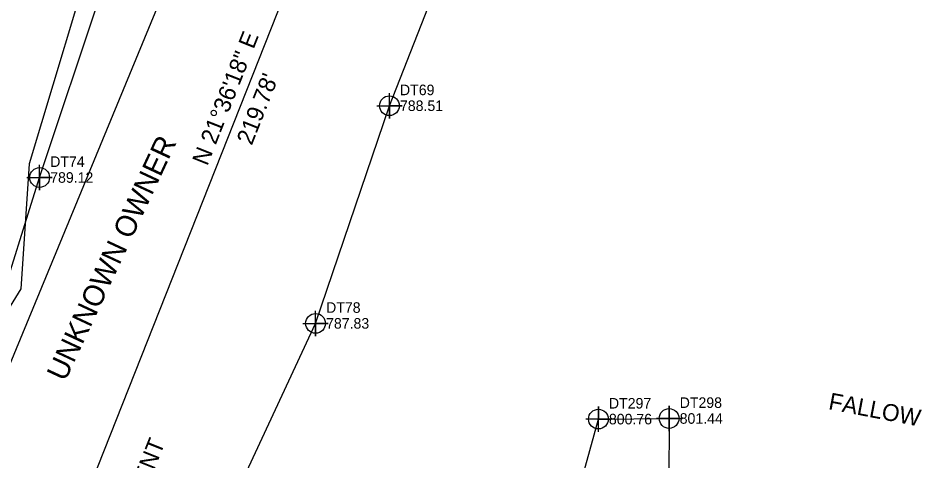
# Model space of a CAD drawing. Extents: x 1316460 to 1321645, y 684173 to 687077.
# Drawn here: x 1319633.3 to 1319847.6, y 686075.6 to 686180.5 of the extents above; entities that cross this region are included whole.
import ezdxf

# ---------------------------------------------------------------- set-up
doc = ezdxf.new("R2010")
doc.units = 0
for name, color, linetype in [('CTL Supplemental Horizontal and Vertical Cogo Elevation', 7, 'Continuous'), ('Exist Hydro Stream or Body of Water Cogo Elevation', 7, 'Continuous'), ('Exist Hydro Stream or Body of Water Cogo Number', 7, 'Continuous'), ('Exist Hydro Stream or Body of Water Cogo Point CELL', 7, 'Continuous'), ('Exist Hydrographic Stream Bed Cogo Number', 7, 'Continuous'), ('Exist Hydrographic Top of Bank Cogo Number', 7, 'Continuous'), ('Exist Hydrographic Top of Bank Cogo Point CELL', 7, 'Continuous'), ('Exist Hydrographic Water Edge Cogo Elevation', 7, 'Continuous'), ('Exist Hydrographic Water Surface Cogo Number', 7, 'Continuous'), ('Exist Property Line', 7, 'Continuous'), ('Exist Property Line Text', 7, 'Continuous'), ('Exist Property Owner Text', 7, 'Continuous'), ('Exist Vegetation Woods Line', 7, 'Continuous'), ('Exist Vegetation Woods Line Text', 7, 'Continuous')]:
    doc.layers.add(name, color=color, linetype=linetype)

msp = doc.modelspace()

# ---------------------------------------------------------------- linework, layer by layer
at = {"layer": 'CTL Supplemental Horizontal and Vertical Cogo Elevation'}
for points in [[(1319770.9, 686082.52), (1319770.9, 686088.52), (1319770.9, 686085.52), (1319773.9, 686085.52), (1319767.9, 686085.52)], [(1319787.68, 686082.67), (1319787.68, 686088.67), (1319787.68, 686085.67), (1319790.68, 686085.67), (1319784.68, 686085.67)]]:
    msp.add_lwpolyline(points, dxfattribs=at)
for centre in [(1319770.9, 686085.52), (1319787.68, 686085.67)]:
    msp.add_circle(centre, 2.34, dxfattribs=at)
at = {"layer": 'Exist Hydro Stream or Body of Water Cogo Point CELL'}
for points in [[(1319718.37, 686159.76), (1319724.37, 686159.76), (1319721.37, 686159.76), (1319721.37, 686156.76), (1319721.37, 686162.76)], [(1319635.45, 686142.76), (1319641.45, 686142.76), (1319638.45, 686142.76), (1319638.45, 686139.76), (1319638.45, 686145.76)], [(1319700.85, 686108.2), (1319706.85, 686108.2), (1319703.85, 686108.2), (1319703.85, 686105.2), (1319703.85, 686111.2)]]:
    msp.add_lwpolyline(points, dxfattribs=at)
for centre in [(1319721.37, 686159.76), (1319638.45, 686142.76), (1319703.85, 686108.2)]:
    msp.add_circle(centre, 2.34, dxfattribs=at)
at = {"layer": 'Exist Hydrographic Water Edge Cogo Elevation'}
for points in [[(1319609.37, 686060.81), (1319617.66, 686076.4), (1319638.45, 686142.76), (1319653.04, 686186.56), (1319674.85, 686240.81)], [(1319671.78, 686037.22), (1319683.32, 686064.04), (1319703.85, 686108.2), (1319721.37, 686159.76), (1319742.31, 686213.15)]]:
    msp.add_lwpolyline(points, dxfattribs=at)
at = {"layer": 'Exist Hydrographic Water Surface Cogo Number'}
for p, q in [((1319763.6, 686058.84), (1319770.9, 686085.52)), ((1319770.9, 686085.52), (1319787.68, 686085.67)), ((1319787.68, 686085.67), (1319787.52, 686046.5))]:
    msp.add_line(p, q, dxfattribs=at)
at = {"layer": 'Exist Property Line'}
for p, q in [((1319623.43, 686079.33), (1319824.68, 686565.61)), ((1319650.35, 686069.59), (1319731.27, 686273.93))]:
    msp.add_line(p, q, dxfattribs=at)
at = {"layer": 'Exist Vegetation Woods Line'}
msp.add_lwpolyline([(1319710.84, 686358.17), (1319684.48, 686276.05), (1319665.93, 686223.9), (1319652.82, 686201.99), (1319635.98, 686145.96), (1319634.02, 686116.41), (1319613.48, 686083.15), (1319563.01, 686080.16)], dxfattribs=at)

# ---------------------------------------------------------------- texts
at = {"layer": 'Exist Hydro Stream or Body of Water Cogo Elevation'}
for s, p in [('788.51', (1319723.87, 686158.51)), ('789.12', (1319640.95, 686141.51)), ('787.83', (1319706.35, 686106.95))]:
    msp.add_text(s, height=2.5, dxfattribs=at).set_placement(p)
at = {"layer": 'Exist Hydro Stream or Body of Water Cogo Number'}
for s, p in [('DT69', (1319723.87, 686162.26)), ('DT74', (1319640.95, 686145.26)), ('DT78', (1319706.35, 686110.7))]:
    msp.add_text(s, height=2.5, dxfattribs=at).set_placement(p)
at = {"layer": 'Exist Hydrographic Stream Bed Cogo Number'}
msp.add_text('BRIDGE BENT', height=4, rotation=68.22, dxfattribs=at).set_placement((1319654.78, 686046.26))
at = {"layer": 'Exist Hydrographic Top of Bank Cogo Number'}
for s, p in [('800.76', (1319773.4, 686084.27)), ('801.44', (1319790.18, 686084.42))]:
    msp.add_text(s, height=2.5, dxfattribs=at).set_placement(p)
at = {"layer": 'Exist Hydrographic Top of Bank Cogo Point CELL'}
for s, p in [('DT297', (1319773.4, 686088.02)), ('DT298', (1319790.18, 686088.17))]:
    msp.add_text(s, height=2.5, dxfattribs=at).set_placement(p)
at = {"layer": 'Exist Property Line Text'}
for s, p in [('N 21%%D36\'18" E', (1319678.2, 686145.35)), ("219.78'", (1319688.73, 686150.21))]:
    msp.add_text(s, height=4, rotation=68.3949, dxfattribs=at).set_placement(p)
at = {"layer": 'Exist Property Owner Text'}
msp.add_text('UNKNOWN OWNER', height=5, rotation=65.0061, dxfattribs=at).set_placement((1319644.48, 686094.23))
at = {"layer": 'Exist Vegetation Woods Line Text'}
msp.add_text('FALLOW', height=4, rotation=349.2157, dxfattribs=at).set_placement((1319825.27, 686087.89))

doc.saveas('drawing.dxf')
